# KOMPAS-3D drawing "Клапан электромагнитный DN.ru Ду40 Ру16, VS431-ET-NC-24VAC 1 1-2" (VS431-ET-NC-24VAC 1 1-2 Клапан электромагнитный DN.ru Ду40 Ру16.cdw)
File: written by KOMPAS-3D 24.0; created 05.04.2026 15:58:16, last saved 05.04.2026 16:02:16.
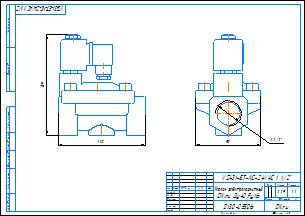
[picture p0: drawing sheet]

Document properties: c3d_UniqueCompID: ef56311e-7521-43dc-8291-0e6108b3d81d; Автор: artio; Класс точности: c; Знак неуказанной шероховатости: Шероховатость не задана; Рассекать на разрезах: Да; c3d_UniqueCompID: ef56311e-7521-43dc-8291-0e6108b3d81d; Автор: artio; Класс точности: c; Знак неуказанной шероховатости: Шероховатость не задана; Рассекать на разрезах: Да; c3d_UniqueCompID: ef56311e-7521-43dc-8291-0e6108b3d81d; Автор: artio; Класс точности: c; Знак неуказанной шероховатости: Шероховатость не задана; Рассекать на разрезах: Да; c3d_UniqueCompID: ef56311e-7521-43dc-8291-0e6108b3d81d; Автор: artio; Класс точности: c; Знак неуказанной шероховатости: Шероховатость не задана; Рассекать на разрезах: Да; Автор: artio; Форматы листов документа: A3; Полное имя файла: VS431-ET-NC-24VAC 1 1-2 Клапан электромагнитный DN.ru Ду40 Ру16.m3d; Масса: 2.285; Наименование: Клапан электромагнитный DN.ru Ду40 Ру16; Количество листов документа: 1; Примечание: D130-05506

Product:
- Body: Тело 1  | qty 1
    Масса: 3.859459
- Part/product: Клапан электромагнитный DN.ru Ду40 Ру16  | designation VS431-ET-NC-24VAC 1 1-2
    Масса: 2.285
    Раздел спецификации: Прочие изделия
    Примечание: D130-05506
    additional columns: ef56311e-7521-43dc-8291-0e6108b3d81d; artio; c; Шероховатость не задана; Да

Views: Вид 1, Спереди
Referenced files in C:\Users\artio\OneDrive\Рабочий стол\Клапан электромагнитный DN.ru\VS431\VS431-ET-NC\: VS431-ET-NC-24VAC 3-4 Клапан электромагнитный DN.ru Ду20 Ру16.m3d, VS431-ET-NC-24VAC 1 1-2 Клапан электромагнитный DN.ru Ду40 Ру16.m3d, VS431-ET-NC-24VAC 3-4 Клапан электромагнитный DN.ru Ду20 Ру16.cdw
Referenced files in C:\Users\artio\OneDrive\Рабочий стол\Клапан электромагнитный DN.ru\VS431\VS431-ET-NC\VS431-ET-NC-24VAC\Ду40\: VS431-ET-NC-24VAC 1 1-2 Клапан электромагнитный DN.ru Ду40 Ру16.m3d
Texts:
  VS431-ET-NC-24VAC 1 1-2
  Клапан электромагнитный
  DN.ru Ду40 Ру16
  VS431-ET-NC-24VAC 1 1/2"
  VS431-ET-NC-24VAC 1 1/2"-
  Клапан электромагнитный DN.ru Ду40 Ру16
  VS431-ET-NC-24VAC 1 1-2 Клапан электромагнитный DN.ru Ду40 Ру16
Dimensions and other numbers on the sheet: 0; 3; 2; 4; 90; 1 1/2"; 1:1; 1; 2,29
